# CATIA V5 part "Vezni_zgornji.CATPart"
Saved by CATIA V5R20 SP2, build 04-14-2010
Part number: Vezni_zgornji
Bounding box of the stored display mesh (mm): x -33 to 33, y -5 to 30, z -9 to 9
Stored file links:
  C:\Documents and Settings\Administrator\My Documents\Hobi_dokumenti\CAD_CNC\Clap_CATIA\Vezni_zgornji.CATPart
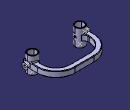
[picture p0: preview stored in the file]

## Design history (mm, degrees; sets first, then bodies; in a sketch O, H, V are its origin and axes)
Set1
  Point1: type Center, Curve edge [start face of Pad4 | face of Pad4 from Sketch5.A2]
  Point2: type Center, Curve edge [start face of Pad4 | face of Pad4 from Sketch5.A1]
  Point3: type Center, Curve edge [face of Pad2 from Sketch3.A1 | end face of Pad2]
  Point4: type Center, Curve edge [face of Mirror1 | face of Pad3]
  Point5: type Center, Curve edge [face of Pad3 | face of Pad2 from Sketch3.A1]
Body1 (main body)
  Sketch1 on xy-plane, origin (0, 0, 0), H (1, 0, 0), V (0, 1, 0)
    line L1 (-10, 30) -> (10, 30)
    line L2 (30, 10) -> (30, -5)
    line L3 (30, -5) -> (-30, -5)
    line L4 (-30, -5) -> (-30, 10)
    reference intersected line E2 through (0, 0) direction (0, 1) from yz-plane
    reference intersected line E3 through (0, 0) direction (-1, 0) from zx-plane
    arc A1 centre (-10, 10) radius 20 from (-10, 30) to (-30, 10) ccw
    arc A2 centre (10, 10) radius 20 from (30, 10) to (10, 30) ccw
    distance E2 L2 = 30
    distance E2 L4 = 30
    distance E3 L3 = 5
    distance E3 L1 = 30
    radius A1 = 20
    radius A2 = 20
    horizontal: L1 H, L3 H, E3 H
    vertical: L2 V, L4 V, E2 V
    perpendicularity: E2 L1
    tangency: A1 L1, A1 L4, A2 L2, A2 L1
  Pad1: profile Sketch1, direction (0, 0, 1), length 3, mirrored extent
  Sketch2 on start face of Pad1, origin (0, 0, -3), H (1, 0, 0), V (0, -1, 0)
    offset line E1 (25, 5) -> (25, -10) from edge [start face of Pad1 | face of Pad1 from Sketch1.L2]
    offset arc E2 centre (10, -10) radius 15 from (10, -25) to (25, -10) ccw from edge [start face of Pad1 | face of Pad1 from Sketch1.A2]
    offset line E3 (10, -25) -> (-10, -25) from edge [start face of Pad1 | face of Pad1 from Sketch1.L1]
    point P6 (-10, -25)
    offset arc E4 centre (-10, -10) radius 15 from (-25, -10) to (-10, -25) ccw from edge [start face of Pad1 | face of Pad1 from Sketch1.A1]
    point P8 (-10, -25)
    offset line E5 (-25, -10) -> (-25, 5) from edge [start face of Pad1 | face of Pad1 from Sketch1.L4]
    line L1 (25, 5) -> (-25, 5)
    coincidence: P8 P6, E4 P6
    tangency: E4 E3, L1 E2
  Pocket1: profile Sketch2, direction (0, 0, 1), length 6
  Sketch3 on face of Pad1 from Sketch1.L4, origin (-30, 0, 0), H (0, -1, 0), V (0, 0, 1)
    circle A1 centre (0, 0) radius 3
    radius A1 = 3
  Pad2: profile Sketch3, direction (-1, 0, 0), length 3
  Mirror1: of Pad2, Sketch3, about yz-plane
  Sketch4 on xy-plane, origin (0, 0, 0), H (1, 0, 0), V (0, 1, 0)
    line L1 (20, -5) -> (20, 5)
    line L2 (20, 5) -> (30, 5)
    point P1 (20, -5)
    point P2 (20, 5)
    point P3 (30, 5)
    line L3 (30, 5) -> (30, -5)
    point P4 (30, -5)
    line L4 (30, -5) -> (20, -5)
    reference projected line E1 (30, -5) -> (30, 10) from edge [face of Pad1 from Sketch1.L2 | end face of Pad1]
    point P5 (-20, -5)
    point P6 (-20, 5)
    point P7 (-30, 5)
    point P8 (-30, -5)
    line L5 (-20, -5) -> (-20, 5)
    line L6 (-20, 5) -> (-30, 5)
    line L7 (-30, 5) -> (-30, -5)
    line L8 (-30, -5) -> (-20, -5)
    length L4 = 10
    distance E1 L3 = 0
    length L1 = 10
    horizontal: L2 H, L4 H
    vertical: L1 V, L3 V
    symmetry: P1 P5 V, P2 P6 V, P3 P7 V, P4 P8 V, L1 L5 V, L2 L6 V, L3 L7 V, L4 L8 V
  Pad3: profile Sketch4, direction (0, 0, 1), length 3, mirrored extent
  Sketch5 on xy-plane, origin (0, 0, 0), H (1, 0, 0), V (0, 1, 0)
    circle A1 centre (25, 0) radius 5
    point P1 (25, 0)
    circle A2 centre (-25, 0) radius 5
    radius A1 = 5
    distance P1 H = 0
    distance V P1 = 25
    symmetry: A1 A2 V
  Pad4: profile Sketch5, direction (0, 0, 1), length 9, mirrored extent
  Fillet1: radius 5, on edge [face of Pad3 | face of Pad3 from Sketch4.L1]; edge [face of Pad3 from Sketch4.L5 | face of Pad3]; edge [face of Pad3 from Sketch4.L1 | face of Pad3 from Sketch4.L2]; edge [face of Pad3 from Sketch4.L6 | face of Pad3 from Sketch4.L5]
  Fillet2: radius 5, on edge [face of Fillet1 | face of Pocket1 from Sketch2.E1]; edge [face of Pocket1 from Sketch2.E5 | face of Fillet1]
  Fillet3: radius 0.5, on edge [face of Pad3 | face of Pad3] (x2)
  Sketch6 on end face of Pad2, origin (-33, 0, 0), H (0, 1, 0), V (0, 0, -1)
    point P1 (0, 0)
    reference projected point E1 (0, 0) from Point3
    coincidence: E1 P1
  Hole1: placed by Sketch6, at (-33, 0, 0) direction (1, 0, 0), diameter 2.4, depth 70, threaded, thread diameter 3, thread depth 10, pitch 1
  Sketch7 on start face of Pad4, origin (-25, 0, -9), H (1, 0, 0), V (0, -1, 0)
    point P1 (0, 0)
    reference projected point E1 (0, 0) from Point1
    coincidence: E1 P1
  Hole2: placed by Sketch7, at (-25, 0, -9) direction (0, 0, 1), diameter 8, depth 25
  Sketch8 on start face of Pad4, origin (25, 0, -9), H (1, 0, 0), V (0, -1, 0)
    point P1 (0, 0)
    reference projected point E1 (0, 0) from Point2
    coincidence: E1 P1
  Hole3: placed by Sketch8, at (25, 0, -9) direction (0, 0, 1), diameter 8, depth 25
  Chamfer1: length 0.5, angle 45, on edge [face of Pad3 | face of Pocket1 from Sketch2.E2]; edge [face of Pad3 | face of Pad1 from Sketch1.L1]; edge [face of Pad1 from Sketch1.L1 | face of Pad3]; edge [face of Pocket1 from Sketch2.E2 | face of Pad3]; edge [face of Pad3 | face of Pad3] (x4)
  Chamfer2: length 0.2, angle 45, on start face of Pad4 (x2); end face of Pad4; edge [face of Pad4 from Sketch5.A1 | end face of Pad4]; edge [end face of Pad4 | face of Hole3]
  Fillet4: radius 1, on edge [face of Pad4 | face of Pad3] (x2); edge [face of Pad3 | face of Pad4] (x2)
